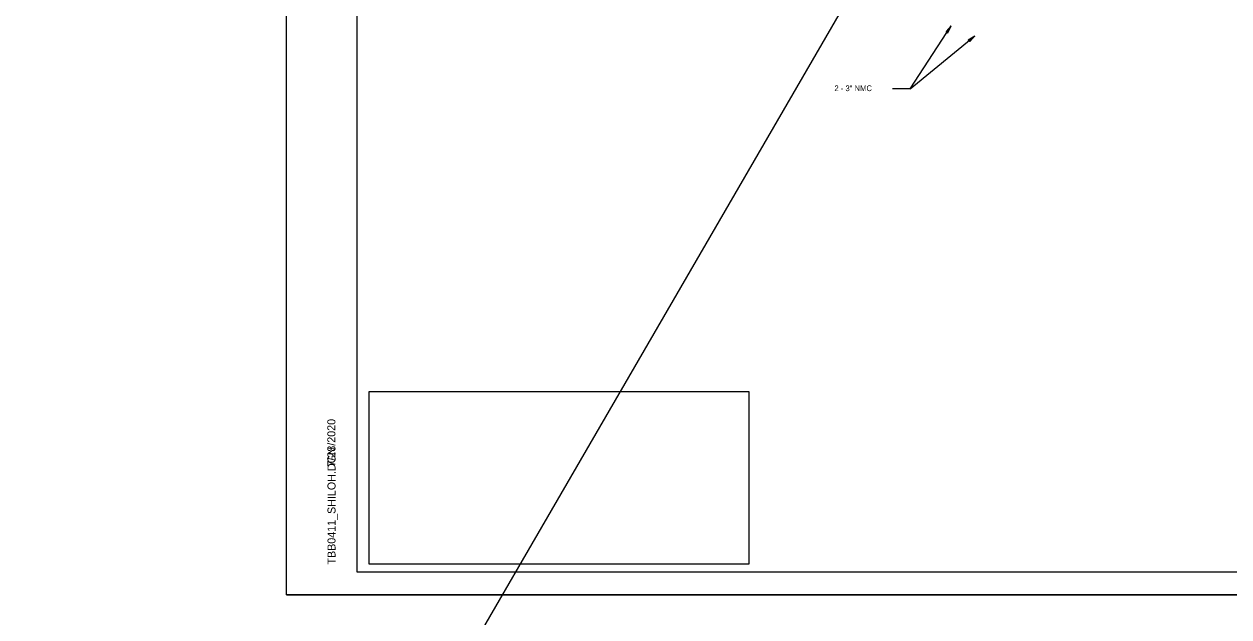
# Model space of a CAD drawing. Extents: x 660063 to 664816, y 641756 to 643817.
# Drawn here: x 661273 to 661905, y 642237 to 642548 of the extents above; entities that cross this region are included whole.
import ezdxf

# ---------------------------------------------------------------- set-up
doc = ezdxf.new("R2010")
doc.units = 0
for name, color, linetype in [('R_Border', 7, 'Continuous'), ('R_No Plot', 7, 'Continuous'), ('T_Drafting', 7, 'Continuous')]:
    doc.layers.add(name, color=color, linetype=linetype)

msp = doc.modelspace()

# ---------------------------------------------------------------- linework, layer by layer
at = {"layer": 'R_Border'}
for p, q in [((661447.99, 642260.59), (661447.99, 642876.97)), ((661447.99, 642260.59), (661447.99, 642260.59)), ((662396.53, 642260.59), (661447.99, 642260.59))]:
    msp.add_line(p, q, dxfattribs=at)
at = {"layer": 'R_No Plot'}
msp.add_line((661410.79, 642248.66), (662410.79, 642248.66), dxfattribs=at)
msp.add_lwpolyline([(661410.77, 642888.66), (662410.79, 642888.66), (662410.79, 642248.64), (661410.77, 642248.64)], close=True, dxfattribs=at)
at = {"layer": 'T_Drafting'}
for p, q in [((661738.16, 642514.22), (661759.67, 642547.2)), ((661756.98, 642544.18), (661759.67, 642547.2)), ((661756.98, 642544.18), (661757.99, 642543.52)), ((661757.07, 642544.13), (661759.3, 642546.64)), ((661757.15, 642544.07), (661758.93, 642546.07)), ((661757.23, 642544.02), (661758.56, 642545.51)), ((661757.32, 642543.96), (661758.19, 642544.94)), ((661757.41, 642543.9), (661757.83, 642544.38)), ((661757.56, 642543.8), (661757.83, 642544.38)), ((661757.65, 642543.75), (661758.19, 642544.94)), ((661757.73, 642543.69), (661758.56, 642545.51)), ((661757.82, 642543.64), (661758.93, 642546.07)), ((661757.9, 642543.58), (661759.3, 642546.64)), ((661757.99, 642543.52), (661759.67, 642547.2)), ((661738.16, 642514.22), (661772.17, 642541.92)), ((661768.69, 642539.86), (661772.17, 642541.92)), ((661768.69, 642539.86), (661769.45, 642538.93)), ((661768.75, 642539.78), (661771.65, 642541.5)), ((661768.82, 642539.7), (661771.12, 642541.06)), ((661768.88, 642539.62), (661770.6, 642540.64)), ((661768.95, 642539.54), (661770.08, 642540.21)), ((661769.01, 642539.46), (661769.56, 642539.79)), ((661769.13, 642539.32), (661769.56, 642539.79)), ((661769.19, 642539.24), (661770.08, 642540.21)), ((661769.26, 642539.16), (661770.6, 642540.64)), ((661769.32, 642539.08), (661771.12, 642541.06)), ((661769.39, 642539), (661771.65, 642541.5)), ((661769.45, 642538.93), (661772.17, 642541.92)), ((661738.16, 642514.22), (661728.94, 642514.22))]:
    msp.add_line(p, q, dxfattribs=at)
msp.add_lwpolyline([(661903.35, 643024.49), (661786.96, 642702.02), (661273.12, 641816.18)], dxfattribs=at)
msp.add_lwpolyline([(661903.35, 643024.49), (661786.96, 642702.02), (661273.12, 641816.18)], dxfattribs=at)
msp.add_lwpolyline([(661903.35, 643024.49), (661786.96, 642702.02), (661273.12, 641816.18)], dxfattribs=at)
msp.add_lwpolyline([(661454.08, 642264.89), (661653.74, 642264.89), (661653.74, 642355.17), (661454.08, 642355.17)], close=True, dxfattribs=at)

# ---------------------------------------------------------------- texts
at = {"layer": 'R_Border'}
for s, p in [('7/28/2020', (661436.47, 642315.98)), ('TBB0411_SHILOH.DGN', (661436.56, 642264.57))]:
    msp.add_text(s, height=4.2, rotation=90, dxfattribs=at).set_placement(p)
at = {"layer": 'T_Drafting'}
msp.add_text('2 - 3" NMC', height=3, dxfattribs=at).set_placement((661698.41, 642512.93))

doc.saveas('drawing.dxf')
